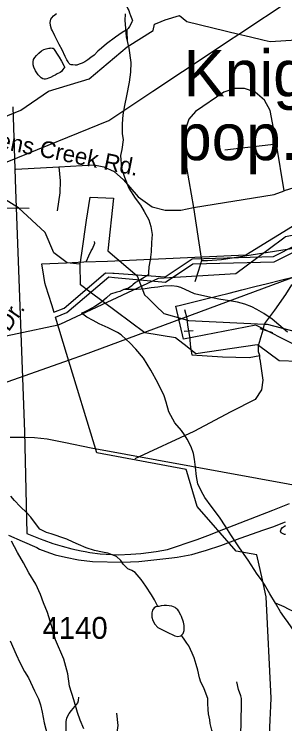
# Model space of a CAD drawing. Extents: x 2169602 to 2449496, y 721995 to 810662.
# Drawn here: x 2389822 to 2391367, y 803829 to 807880 of the extents above; entities that cross this region are included whole.
import ezdxf

# ---------------------------------------------------------------- set-up
doc = ezdxf.new("R2010")
doc.units = 0
doc.layers.add('Default', color=7, linetype='Continuous')

msp = doc.modelspace()

# ---------------------------------------------------------------- linework, layer by layer
at = {"layer": 'Default'}
for p, q in [((2391104.4, 807766.5), (2391403.4, 807965.4)), ((2390638, 807828), (2390683.2, 807847.1)), ((2391045.2, 807727.1), (2391104.4, 807766.5)), ((2391104.4, 807766.5), (2391139.4, 807758)), ((2390952.7, 807665.6), (2391045.2, 807727.1)), ((2391139.4, 807758), (2391226.9, 807736.9)), ((2391226.9, 807736.9), (2391248.6, 807731.6)), ((2390614, 807440.2), (2390952.7, 807665.6)), ((2389738.3, 806774.5), (2389907.2, 806772.6)), ((2390208.4, 806515.3), (2390236, 806704.5)), ((2391279.7, 806542.7), (2391361.7, 806603.8)), ((2390199.2, 806453), (2390208.4, 806515.3)), ((2390199.2, 806453), (2390178.2, 806455.2)), ((2390403.7, 806183.7), (2390255.8, 806293.5)), ((2390586.6, 806258.9), (2390631.6, 806214.7)), ((2390794.8, 806194.8), (2390807.3, 806144.9)), ((2390807.3, 806144.9), (2390812.3, 806105)), ((2391240.8, 806070.9), (2391251.7, 806110.4)), ((2390844.5, 806071.9), (2390792.7, 806069.6)), ((2391298.7, 806060.4), (2391227, 806083.8)), ((2390822.2, 806040.1), (2390829.7, 805977.7)), ((2391216.4, 805988.1), (2391228.4, 806026.7)), ((2390829.7, 805977.7), (2390837.2, 805935.2))]:
    msp.add_line(p, q, dxfattribs=at)
for points in [[(2391248.6, 807731.6), (2391283.1, 807723.3), (2391433.2, 807733.3), (2391715.2, 807986.7), (2391890.1, 808012.7), (2392243, 808142)], [(2390444.5, 807966.8), (2390460.3, 807937.2), (2390470.5, 807911.3), (2390476.9, 807901.4), (2390481, 807887.4), (2390486.7, 807873.2), (2390490.6, 807863.2), (2390494.7, 807853.3), (2390497, 807843.2), (2390494.7, 807835.4), (2390489, 807823.3), (2390481.2, 807809.1), (2390473.2, 807797.3), (2390465.4, 807791.2)], [(2390465.4, 807791.2), (2390461.3, 807789.4), (2390439.4, 807774.8), (2390401.4, 807749), (2390350, 807710.5), (2390320, 807686.2), (2390299.9, 807668.2), (2390278, 807646.3), (2390260.3, 807632), (2390242.3, 807620.1), (2390226.1, 807607.9), (2390210.3, 807599.8), (2390192.3, 807593.6), (2390180.2, 807589.7), (2390170.3, 807589.6), (2390156.2, 807591.3), (2390148.2, 807591.3), (2390142.6, 807593.4), (2390138.5, 807597.2), (2390134.6, 807599.5), (2390130.5, 807607.4), (2390122.1, 807619.2), (2390114.1, 807639.1), (2390095.7, 807677.1), (2390079.9, 807707.1), (2390053.4, 807757), (2390041.3, 807784.7), (2390035, 807794.6), (2390029.5, 807814.5), (2390027.4, 807832.7), (2390029, 807842.6), (2390030.7, 807850.9), (2390037.2, 807858.8), (2390046.9, 807870.7), (2390062.9, 807882.9)], [(2390455.5, 807881.3), (2390453.8, 807843), (2390457.9, 807799.4), (2390462.2, 807751.3), (2390476.4, 807685.4), (2390488.7, 807603.3), (2390486.8, 807549.6), (2390479.5, 807491.5), (2390463.5, 807413.2), (2390451.8, 807359.4), (2390441.9, 807305.3), (2390438.5, 807253.1), (2390438.5, 807199.2), (2390444.8, 807163.3), (2390437, 807107.3), (2390428.8, 807073.3), (2390435.6, 807001.2), (2390451.6, 806949.4), (2390476.2, 806887.6), (2390512.5, 806829.8), (2390542.4, 806790), (2390564.4, 806754.2), (2390590.8, 806706), (2390602.7, 806668.1), (2390609.1, 806622.1), (2390607, 806576.2), (2390603.5, 806524.3), (2390598, 806478.1), (2390591.6, 806438.1), (2390588.1, 806406.2), (2390588.3, 806392.4)], [(2390683.2, 807847.1), (2390766.2, 807871.7), (2390808.2, 807838), (2391104.4, 807766.5)], [(2389390, 807062.1), (2389404.3, 807089.3), (2389570.1, 807148.2), (2389678.2, 807257.6), (2389861.1, 807332.4), (2390018.2, 807440.8), (2390251.1, 807511.5), (2390467.2, 807694.1), (2390616.1, 807786.1), (2390624.1, 807822.1), (2390638, 807828)], [(2390465.4, 807791.2), (2390465.2, 807777.1), (2390465.4, 807761.2), (2390467.4, 807747.1), (2390467.2, 807731.3)], [(2390110.5, 807579.2), (2390100.6, 807563.2), (2390092.6, 807553.1), (2390084.6, 807547), (2390068.4, 807538.9), (2390056.5, 807530.9), (2390046.9, 807528.8), (2390029, 807518.9), (2390019, 807514.7), (2390009, 807510.6), (2390001, 807508.5), (2389993, 807508.5), (2389985.2, 807510.5), (2389976.8, 807516.6), (2389966.9, 807526.3), (2389958.9, 807534.4), (2389944.8, 807556.4), (2389934.3, 807578.3), (2389930.4, 807590.2), (2389930.4, 807600.3), (2389930.4, 807608.4), (2389932.5, 807620.3), (2389940.3, 807632.1), (2389950.1, 807644.4), (2389962.2, 807656.4), (2389978.2, 807670.6), (2389991.9, 807678.7), (2390005.7, 807682.6), (2390012, 807684.5), (2390020, 807686.6), (2390028, 807686.6), (2390034, 807686.9), (2390039.9, 807686.8), (2390044, 807685), (2390050.2, 807678.8), (2390053.9, 807672.9), (2390068, 807650.9), (2390078.1, 807635.2), (2390092.4, 807611.1), (2390100.6, 807599.3), (2390106.4, 807585.1), (2390110.5, 807579.2)], [(2389782, 807036.7), (2390362.2, 807272.7), (2390614, 807440.2)], [(2391320.4, 807137), (2391283.3, 807330.5), (2391251.5, 807388.8), (2391198.5, 807433.8), (2391137.6, 807455.1), (2391079.3, 807455.1), (2391018.4, 807433.8), (2390856.8, 807325.2), (2390819.7, 807280.1), (2390803.8, 807235), (2390801.2, 807160.8), (2390806.5, 807036.2), (2390806.5, 807004.4), (2390846.2, 806776.5)], [(2389814.4, 807351.3), (2389830.2, 806879.2), (2389880.7, 805496), (2389894.4, 804915.9), (2389969.7, 804885.4), (2389990.9, 804877), (2390043.4, 804858.9), (2390096.7, 804842.9), (2390150.4, 804828.9), (2390204.7, 804816.9), (2390226.9, 804812.6), (2390253.4, 804807), (2390313.7, 804799.6), (2390417.7, 804794.7), (2390488.9, 804796.9)], [(2389814.4, 807351.3), (2389830.2, 806879.2), (2389880.7, 805496), (2389894.4, 804915.9), (2389969.7, 804885.4), (2389990.9, 804877), (2390043.4, 804858.9), (2390096.7, 804842.9), (2390150.4, 804828.9), (2390204.7, 804816.9), (2390226.9, 804812.6), (2390253.4, 804807), (2390313.7, 804799.6), (2390417.7, 804794.7), (2390488.9, 804796.9)], [(2391320.4, 807137), (2391025.3, 807102.8)], [(2391362.8, 806871.9), (2391320.4, 807137)], [(2389831.1, 806995.4), (2390077.5, 807008.7)], [(2390077.5, 807008.7), (2390085.4, 806929.1), (2390082.8, 806860.2), (2390066.9, 806756.8)], [(2390077.5, 807008.7), (2390276.1, 807019.3), (2390334.4, 807008.7), (2390392.7, 806982.2), (2390445.7, 806934.4), (2390530.4, 806836.4), (2390609.9, 806780.7), (2390684.1, 806762.1), (2390774.2, 806762.1), (2390846.2, 806776.5)], [(2390178.2, 806455.2), (2390124.2, 806461), (2390049.1, 806518.3), (2389998.3, 806634.2), (2389847.2, 806775.1), (2389564.5, 806948.2)], [(2391474.4, 806906), (2391362.8, 806871.9)], [(2390236, 806704.5), (2390255.2, 806835.6), (2390388.3, 806829.6), (2390357.1, 806528.4), (2390524.2, 806387.2), (2390567.1, 806278.1), (2390586.6, 806258.9)], [(2390846.2, 806776.5), (2391307.1, 806850.7), (2391362.8, 806871.9)], [(2391643.7, 806811.6), (2391144.7, 806504.4), (2390354.5, 806467.6), (2390219, 806463.9), (2390121, 806459.1), (2389978.5, 806452.2), (2389983.2, 806421.3), (2389995.7, 806348.6), (2390001.7, 806328.9), (2390035.2, 806222.1)], [(2391643.7, 806811.6), (2391144.7, 806504.4), (2390354.5, 806467.6), (2390219, 806463.9), (2390121, 806459.1), (2389978.5, 806452.2), (2389983.2, 806421.3), (2389995.7, 806348.6), (2390001.7, 806328.9), (2390035.2, 806222.1)], [(2390846.2, 806776.5), (2390891.2, 806474.3)], [(2390035.2, 806222.1), (2390048.7, 806178.7), (2390107.5, 806202.6), (2390344.2, 806402.9), (2390384.7, 806402.4), (2390392.2, 806402.4), (2390684, 806380.3), (2390838, 806484), (2391302.5, 806496.6), (2391569.5, 806631.3)], [(2390035.2, 806222.1), (2390048.7, 806178.7), (2390107.5, 806202.6), (2390344.2, 806402.9), (2390384.7, 806402.4), (2390392.2, 806402.4), (2390684, 806380.3), (2390838, 806484), (2391302.5, 806496.6), (2391569.5, 806631.3)], [(2391361.7, 806603.8), (2391371, 806610.8), (2391504.1, 806637.6), (2391527.1, 806628.9)], [(2391276.5, 803674.9), (2391284.2, 803851.9), (2391285, 803890.7), (2391287.5, 803931.9), (2391289.5, 803975.5), (2391260.2, 804554.3), (2391239, 804651.2), (2391207.5, 804794.6), (2391088.7, 804815.3), (2390866.5, 805069.6), (2390808.2, 805269.7), (2390804.7, 805281.8), (2390295, 805377), (2390121.5, 805942.6), (2390057.7, 806150.1), (2390123.2, 806176.6), (2390363.5, 806380), (2390395.5, 806377.1), (2390686.7, 806350.1), (2390843, 806454.1), (2391306.5, 806466.6), (2391580.7, 806603.4)], [(2391276.5, 803674.9), (2391284.2, 803851.9), (2391285, 803890.7), (2391287.5, 803931.9), (2391289.5, 803975.5), (2391260.2, 804554.3), (2391239, 804651.2), (2391207.5, 804794.6), (2391088.7, 804815.3), (2390866.5, 805069.6), (2390808.2, 805269.7), (2390804.7, 805281.8), (2390295, 805377), (2390121.5, 805942.6), (2390057.7, 806150.1), (2390123.2, 806176.6), (2390363.5, 806380), (2390395.5, 806377.1), (2390686.7, 806350.1), (2390843, 806454.1), (2391306.5, 806466.6), (2391580.7, 806603.4)], [(2390891.2, 806474.3), (2390925.7, 806474.3), (2391005.1, 806479.6), (2391744.2, 806596.2)], [(2390234.7, 806470.4), (2390248.2, 806500.4), (2390262.2, 806528.3), (2390270.2, 806540.5), (2390282.3, 806572.3), (2390280.2, 806582.4)], [(2390089.1, 806113.3), (2390647, 806373), (2391088.1, 806400), (2391279.7, 806542.7)], [(2391829.1, 806529.8), (2391614.3, 806442.5), (2391490.6, 806405), (2390221, 805935.1), (2390136.1, 805905.1)], [(2391251.7, 806110.4), (2391253, 806114.9), (2391311.1, 806190.5), (2391373.5, 806280.3), (2391407.2, 806335.2), (2391472, 806377.7), (2391578.1, 806407.6), (2391679.1, 806467.5), (2391790.8, 806523.2)], [(2390891.2, 806474.3), (2390875.3, 806416), (2390854.2, 806352.3)], [(2390255.8, 806293.5), (2390200.3, 806334.8), (2390199.2, 806453)], [(2390588.3, 806392.4), (2390544.5, 806366.2), (2390514.1, 806348), (2390500.4, 806335.9), (2390494.2, 806329.9), (2390474.3, 806315.9), (2390448.5, 806307.7)], [(2391434.9, 805986.7), (2391201.2, 806104.6), (2390788.7, 806024.3), (2390744.2, 806212.4), (2390763.7, 806217.2), (2390923.9, 806257), (2391049.4, 806288.2), (2391122.4, 806306.4), (2391195.4, 806324.6), (2391268.4, 806342.8), (2391341.7, 806360.9), (2391413.7, 806378.8)], [(2391434.9, 805986.7), (2391201.2, 806104.6), (2390788.7, 806024.3), (2390744.2, 806212.4), (2390763.7, 806217.2), (2390923.9, 806257), (2391049.4, 806288.2), (2391122.4, 806306.4), (2391195.4, 806324.6), (2391268.4, 806342.8), (2391341.7, 806360.9), (2391413.7, 806378.8)], [(2390448.5, 806307.7), (2390436.6, 806303.4), (2390424.5, 806297.5), (2390408.7, 806293.4), (2390372.6, 806281.4), (2390348.8, 806261.1), (2390320.6, 806237), (2390283, 806211), (2390244.9, 806190.8), (2390217, 806176.8), (2390207, 806172.6)], [(2391383.3, 806065.6), (2391333.1, 806107.3), (2391295, 806139.5), (2391246.8, 806171.1), (2391207, 806195), (2391178.7, 806209), (2391138.3, 806224.8), (2391096.5, 806236.4), (2391050.7, 806244.1), (2390990.7, 806254), (2390928.5, 806265.9), (2390852.5, 806283.5), (2390774.1, 806319.2), (2390752.6, 806324.9), (2390720, 806328.7), (2390676.3, 806326.7), (2390642.1, 806322.6), (2390604.3, 806318.2), (2390570.7, 806312.3), (2390522.3, 806307.9), (2390448.5, 806307.7)], [(2390631.6, 806214.7), (2390676.2, 806170.9), (2390785.7, 806140.6)], [(2391314, 804518.1), (2391281.6, 804571.6), (2391251.7, 804623.7), (2391233.4, 804651.5), (2391209.2, 804683.2), (2391158.8, 804763), (2391109, 804833.1), (2391058.5, 804908.8), (2391030, 804954.5), (2390993.9, 805008.2), (2390947.6, 805072), (2390911.3, 805122.1), (2390891, 805156), (2390871.1, 805199.6), (2390863.3, 805241.7), (2390856.8, 805293.9), (2390852.5, 805339.5), (2390846.7, 805371.6), (2390832.2, 805409.5), (2390810.2, 805453.5), (2390794, 805479.4), (2390778, 805503.3), (2390739.9, 805547.2), (2390705.4, 805610.8), (2390689.4, 805664.8), (2390678.8, 805700.8), (2390642.9, 805776.5), (2390602.7, 805848.3), (2390560.5, 805916.3), (2390516, 805968.1), (2390481.5, 806003.7), (2390461.8, 806023.7), (2390433.5, 806049.5), (2390411.6, 806063.4), (2390359.3, 806089.1), (2390307.2, 806112.8), (2390273.2, 806130.9), (2390237.3, 806150.6), (2390207, 806172.6)], [(2390809.3, 805980.3), (2390743.2, 806031.7), (2390568.1, 806061.6), (2390403.7, 806183.7)], [(2389604.1, 806007.4), (2390073.1, 806105.9), (2390089.1, 806113.3)], [(2390785.7, 806140.6), (2390817.3, 806131.9), (2391251.7, 806110.4)], [(2390812.3, 806105), (2390817.2, 806072.5), (2390822.2, 806040.1)], [(2391251.7, 806110.4), (2391267.2, 806109.6), (2391434.3, 806066.8), (2391551.1, 805959.4), (2391552.2, 805893.8), (2391335.2, 805901.5), (2391216.4, 805988.1)], [(2391228.4, 806026.7), (2391229.1, 806028.7), (2391240.8, 806070.9)], [(2391216.4, 805988.1), (2391210.1, 805992.6), (2390860.1, 805940.8), (2390809.3, 805980.3)], [(2391224.5, 805911.4), (2391224.5, 805931.3), (2391217.3, 805952.9), (2391216.4, 805988.1)], [(2390136.1, 805905.1), (2389298.4, 805610), (2388920.7, 805329.7), (2388497.6, 805078.4), (2387721.8, 804600.3), (2387440.6, 804442.1), (2387273.5, 804387.5), (2387010.3, 804326.9), (2386563.9, 804210.1), (2386021, 804063.2), (2385946.7, 804043.4)], [(2391224.5, 805911.4), (2391240.8, 805790.5), (2391233.5, 805736.3), (2391197.5, 805680.4), (2391058.6, 805610), (2390847.6, 805498.1), (2390511.7, 805341.4)], [(2390837.2, 805935.2), (2391011.7, 805924), (2391163.2, 805920.4), (2391224.5, 805931.3)], [(2389799.4, 805465.7), (2389881.4, 805466), (2389937.4, 805462.9), (2390011.2, 805455.4), (2390114.8, 805435.2), (2390262.1, 805404.2), (2391583.9, 805163.1)], [(2390641.7, 804499.1), (2390623.3, 804537.2), (2390605.4, 804565), (2390573.3, 804614.5), (2390547, 804652.6), (2390512.8, 804692.2), (2390494.7, 804704.2), (2390470.9, 804714), (2390444.7, 804739.8), (2390430.5, 804761.9), (2390406.1, 804783.8), (2390356.3, 804803.5), (2390326.2, 804809.3), (2390280.2, 804819.1), (2390233.9, 804834.6), (2390190.2, 804852.5), (2390159.7, 804866.1), (2390121.9, 804884), (2390093.8, 804891.9), (2390055.7, 804905.8), (2390033.8, 804913.6), (2390007.3, 804921.2), (2389969.4, 804941.1), (2389943.3, 804973.1), (2389917.5, 805009), (2389894.9, 805032.7), (2389856.6, 805070.5), (2389824.4, 805104.2), (2389802.5, 805128.2)], [(2390488.9, 804796.9), (2390545.4, 804801.3), (2390631.9, 804812.1), (2390697.4, 804825.3), (2390865.9, 804881.2), (2390927.2, 804903.9), (2391019.9, 804939.8), (2391206.2, 805012.6), (2391299.2, 805049.1), (2391394.4, 805086.9)], [(2390488.9, 804796.9), (2390545.4, 804801.3), (2390631.9, 804812.1), (2390697.4, 804825.3), (2390865.9, 804881.2), (2390927.2, 804903.9), (2391019.9, 804939.8), (2391206.2, 805012.6), (2391299.2, 805049.1), (2391394.4, 805086.9)], [(2389789.7, 804905.4), (2389868, 804872.2), (2389952.4, 804835.1), (2389966.4, 804827.2), (2390002.8, 804813.5), (2390057, 804794.2), (2390115.1, 804780.8), (2390189.1, 804765.5), (2390269.4, 804756.4), (2390439.4, 804752.1), (2390533.5, 804755.2), (2390723.1, 804777.1), (2390753.2, 804781.5), (2390837.1, 804796.4), (2390874.9, 804806.8), (2390920.8, 804821.3), (2391002.5, 804848), (2391112.2, 804889.1), (2391247.7, 804936.6), (2391298.4, 804953.5), (2391371, 804982.2)], [(2391371.3, 804909.2), (2391365.4, 804909.2), (2391357, 804912.9), (2391346.9, 804918.9), (2391343, 804928.9), (2391346.7, 804940.9), (2391354.9, 804949), (2391364.8, 804957.2), (2391370.9, 804961.1)], [(2390219.7, 803801.3), (2390199.6, 803851), (2390183.2, 803893.3), (2390162.7, 803966.9), (2390138.7, 804044.8), (2390128.2, 804114.9), (2390106.1, 804198.6), (2390057.3, 804308.2), (2390035.1, 804390.3), (2390012.6, 804464.2), (2389990.4, 804520.3), (2389972.6, 804568.1), (2389946.1, 804626), (2389905.5, 804691.8), (2389875.8, 804747.4), (2389841.5, 804807.3), (2389807.1, 804871)], [(2390641.7, 804499.1), (2390631.5, 804497), (2390621.6, 804491.2), (2390612, 804478.8), (2390607.9, 804462.8), (2390608.3, 804438.9), (2390614.3, 804418.9), (2390624.5, 804399.1), (2390642.6, 804378.9), (2390672.7, 804363.4), (2390698.7, 804351.4), (2390730.9, 804335.5), (2390738.7, 804331.5), (2390756.8, 804327.9), (2390772.8, 804332), (2390776.9, 804335.9)], [(2390776.9, 804335.9), (2390786.7, 804344.1), (2390792.7, 804361.9), (2390792.7, 804389.8), (2390788.4, 804410), (2390777.9, 804442), (2390774.2, 804449.9), (2390759.9, 804473.9), (2390756.2, 804479.8), (2390747.8, 804487.5), (2390741.6, 804493.8), (2390721.5, 804501.6), (2390707.8, 804503.3), (2390691.6, 804505.3), (2390677.6, 804505.4), (2390661.4, 804503.4), (2390647.7, 804499), (2390641.7, 804499.1)], [(2391624.1, 804412.8), (2391580.8, 804415.2), (2391548.6, 804416.9), (2391526.3, 804423.1), (2391484.4, 804438.8), (2391452.2, 804452.5), (2391420.4, 804468.3), (2391388.3, 804484.1), (2391363.9, 804496.3), (2391314, 804518.1)], [(2391625.9, 804084.7), (2391616.1, 804094.7), (2391589.8, 804133.2), (2391565.6, 804177), (2391541.4, 804215.1), (2391507, 804262.9), (2391463.1, 804308.5), (2391420.9, 804358.3), (2391386.6, 804408.1), (2391366.3, 804436.3), (2391342.1, 804468), (2391314, 804518.1)], [(2390924.5, 803982.9), (2390904.4, 804034.6), (2390888.4, 804066.7), (2390880, 804092.7), (2390869.8, 804136.4), (2390861.6, 804168.5), (2390849.7, 804206.4), (2390839, 804232.4), (2390829.2, 804254.2), (2390818.9, 804274.4), (2390807, 804289.9), (2390792.9, 804311.9), (2390782.4, 804326.1), (2390776.9, 804335.9)], [(2389799.5, 804302.2), (2389834.1, 804225.2), (2389854.6, 804179.4), (2389880.8, 804128.9), (2389904.2, 804091.5), (2389938.4, 804018.3), (2389960.9, 803972.6), (2389973.2, 803936.8), (2389981.7, 803896.8), (2389994.3, 803835), (2390002.7, 803799), (2390023.5, 803721.2), (2390035.9, 803689.3), (2390096.7, 803574.1)], [(2391104.8, 803107.3), (2391117.2, 803857.5), (2391120.4, 803927.7), (2391120.3, 803959.7), (2391119.2, 803974.7), (2391115.9, 803989.6), (2391103.4, 804025.4), (2391093.5, 804069.4)], [(2390096.7, 803574.1), (2390108.6, 803590.6), (2390112.8, 803600.2), (2390115.7, 803614.7), (2390116.7, 803630.3), (2390118.3, 803660.2), (2390117.9, 803682.2), (2390118.2, 803842.2), (2390122.2, 803860.7), (2390127.9, 803874.4), (2390136.6, 803888.2), (2390149.7, 803904.6), (2390169.4, 803928.8), (2390180, 803941.3), (2390185.2, 803949), (2390188.8, 803961.6), (2390191.8, 803980.7)], [(2391016.8, 803617.3), (2391014.9, 803621.6), (2391004.5, 803645.5), (2390994.6, 803663.2), (2390986.2, 803679.1), (2390978.4, 803701.4), (2390970.4, 803719.2), (2390962, 803745.3), (2390957.5, 803765), (2390949.9, 803792.9), (2390941.3, 803831.1), (2390939.5, 803852.9), (2390931.1, 803887), (2390929.2, 803910.8), (2390926.8, 803944.9), (2390928.4, 803973), (2390924.5, 803982.9)], [(2390322.5, 803229.6), (2390315, 803382.8), (2390315, 803487), (2390328.9, 803542.7), (2390374, 803653.9), (2390405.3, 803737.3), (2390415.7, 803820.7), (2390408.8, 803890.2)]]:
    msp.add_lwpolyline(points, dxfattribs=at)

# ---------------------------------------------------------------- texts
for s, height, p in [('Knightdale', 265, (2390788.5, 807410)), ('pop. 10,967', 265, (2390752.8, 807046.6)), ('4140', 125, (2389984.2, 804314.4))]:
    msp.add_text(s, height=height, dxfattribs=at).set_placement(p)
for s, rotation, p in [('Harmens Creek Rd.', 348.6004, (2389421.3, 807178)), ('Dr.', 55.131, (2389791.1, 806063.3))]:
    msp.add_text(s, height=95, rotation=rotation, dxfattribs=at).set_placement(p)

doc.saveas('drawing.dxf')
